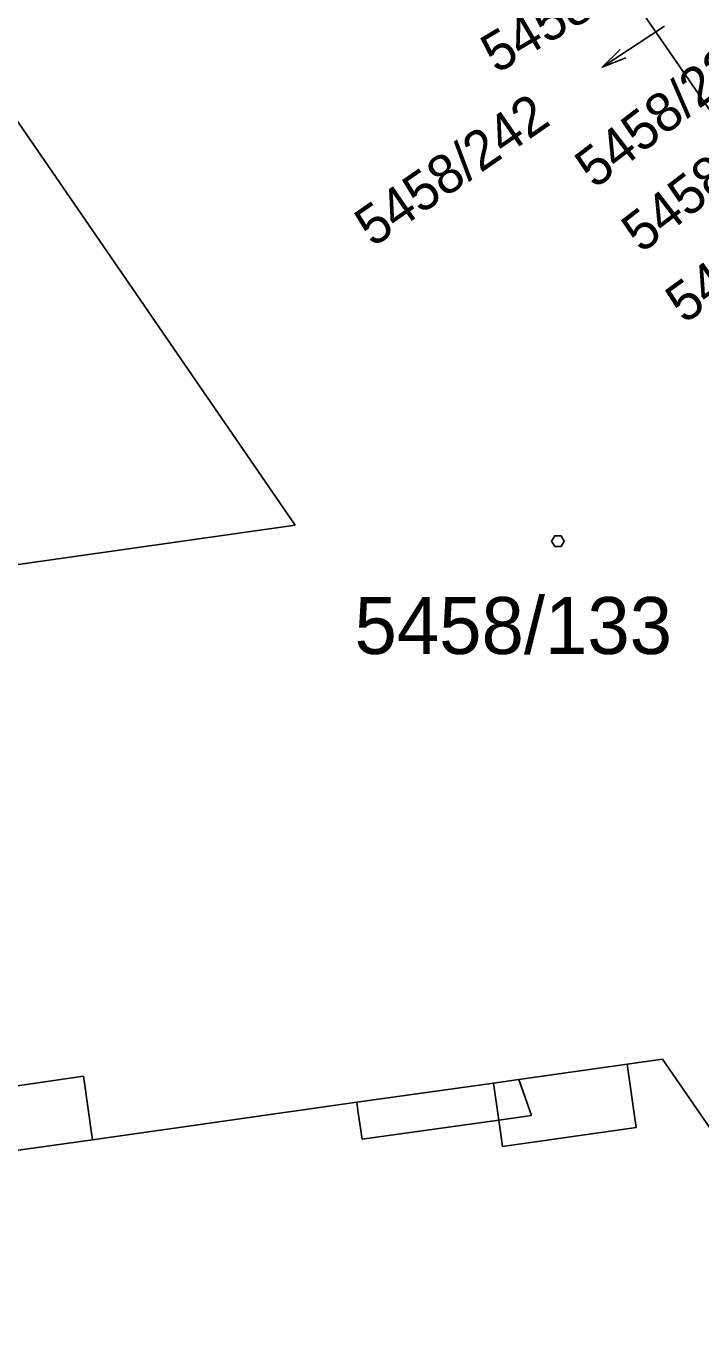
# Model space of a CAD drawing. Extents: x -263587 to -261993, y -1238795 to -1236748.
# Drawn here: x -262822.15 to -262803.18, y -1237239.39 to -1237202.79 of the extents above; entities that cross this region are included whole.
import ezdxf

# ---------------------------------------------------------------- set-up
doc = ezdxf.new("R2010")
doc.units = 0
doc.layers.add('Vrstva 1', color=7, linetype='Continuous')

msp = doc.modelspace()

# ---------------------------------------------------------------- linework, layer by layer
at = {"layer": 'Vrstva 1'}
for p, q in [((-262821.46, -1237178.23), (-262797.76, -1237212.68)), ((-262797.76, -1237212.68), (-262821.46, -1237178.23)), ((-262814.58, -1237216.81), (-262829.77, -1237194.74)), ((-262829.77, -1237194.74), (-262814.58, -1237216.81)), ((-262805.293, -1237203.686), (-262805.955, -1237203.953)), ((-262822.56, -1237217.94), (-262814.58, -1237216.81)), ((-262814.58, -1237216.81), (-262822.56, -1237217.94)), ((-262804.26, -1237231.81), (-262805.25, -1237231.95)), ((-262805.25, -1237231.95), (-262804.26, -1237231.81)), ((-262795.8, -1237244.11), (-262804.26, -1237231.81)), ((-262804.26, -1237231.81), (-262795.8, -1237244.11)), ((-262820.53, -1237232.29), (-262824.24, -1237232.82)), ((-262820.28, -1237234.07), (-262820.53, -1237232.29)), ((-262805.25, -1237231.95), (-262808.3, -1237232.38)), ((-262805.25, -1237231.95), (-262805, -1237233.73)), ((-262805, -1237233.73), (-262805.25, -1237231.95)), ((-262812.85, -1237233.02), (-262809.01, -1237232.48)), ((-262809.01, -1237232.48), (-262808.3, -1237232.38)), ((-262808.86, -1237233.52), (-262809.01, -1237232.48)), ((-262808.3, -1237232.38), (-262807.94, -1237233.39)), ((-262812.85, -1237233.02), (-262820.28, -1237234.07)), ((-262820.28, -1237234.07), (-262812.85, -1237233.02)), ((-262812.81, -1237233.32), (-262812.85, -1237233.02)), ((-262812.85, -1237233.02), (-262812.81, -1237233.32)), ((-262812.7, -1237234.06), (-262812.81, -1237233.32)), ((-262812.81, -1237233.32), (-262812.7, -1237234.06)), ((-262807.94, -1237233.39), (-262808.86, -1237233.52)), ((-262808.86, -1237233.52), (-262812.7, -1237234.06)), ((-262812.7, -1237234.06), (-262808.86, -1237233.52)), ((-262808.76, -1237234.26), (-262808.86, -1237233.52)), ((-262808.86, -1237233.52), (-262808.76, -1237234.26)), ((-262805, -1237233.73), (-262808.76, -1237234.26)), ((-262808.76, -1237234.26), (-262805, -1237233.73)), ((-262820.28, -1237234.07), (-262828.79, -1237235.26)), ((-262828.79, -1237235.26), (-262820.28, -1237234.07))]:
    msp.add_line(p, q, dxfattribs=at)
msp.add_lwpolyline([(-262804.2, -1237202.8), (-262805.955, -1237203.953), (-262805.447, -1237203.452)], dxfattribs=at)
msp.add_lwpolyline([(-262807.11, -1237217.11), (-262807.02, -1237217.26), (-262807.11, -1237217.41), (-262807.29, -1237217.41), (-262807.38, -1237217.26), (-262807.29, -1237217.11)], close=True, dxfattribs=at)

# ---------------------------------------------------------------- texts
for s, rotation, p in [('5458/223', 30.5387, (-262808.927, -1237204.146)), ('5458/224', 37.5287, (-262806.165, -1237207.386)), ('5458/242', 34.6639, (-262812.402, -1237209.025)), ('5458/225', 37.5287, (-262804.855, -1237209.196)), ('5458/226', 35.9817, (-262803.645, -1237211.179))]:
    msp.add_text(s, height=1.1, rotation=rotation, dxfattribs=at).set_placement(p)
msp.add_text('5458/133', height=1.6, dxfattribs=at).set_placement((-262812.916, -1237220.43))

doc.saveas('drawing.dxf')
